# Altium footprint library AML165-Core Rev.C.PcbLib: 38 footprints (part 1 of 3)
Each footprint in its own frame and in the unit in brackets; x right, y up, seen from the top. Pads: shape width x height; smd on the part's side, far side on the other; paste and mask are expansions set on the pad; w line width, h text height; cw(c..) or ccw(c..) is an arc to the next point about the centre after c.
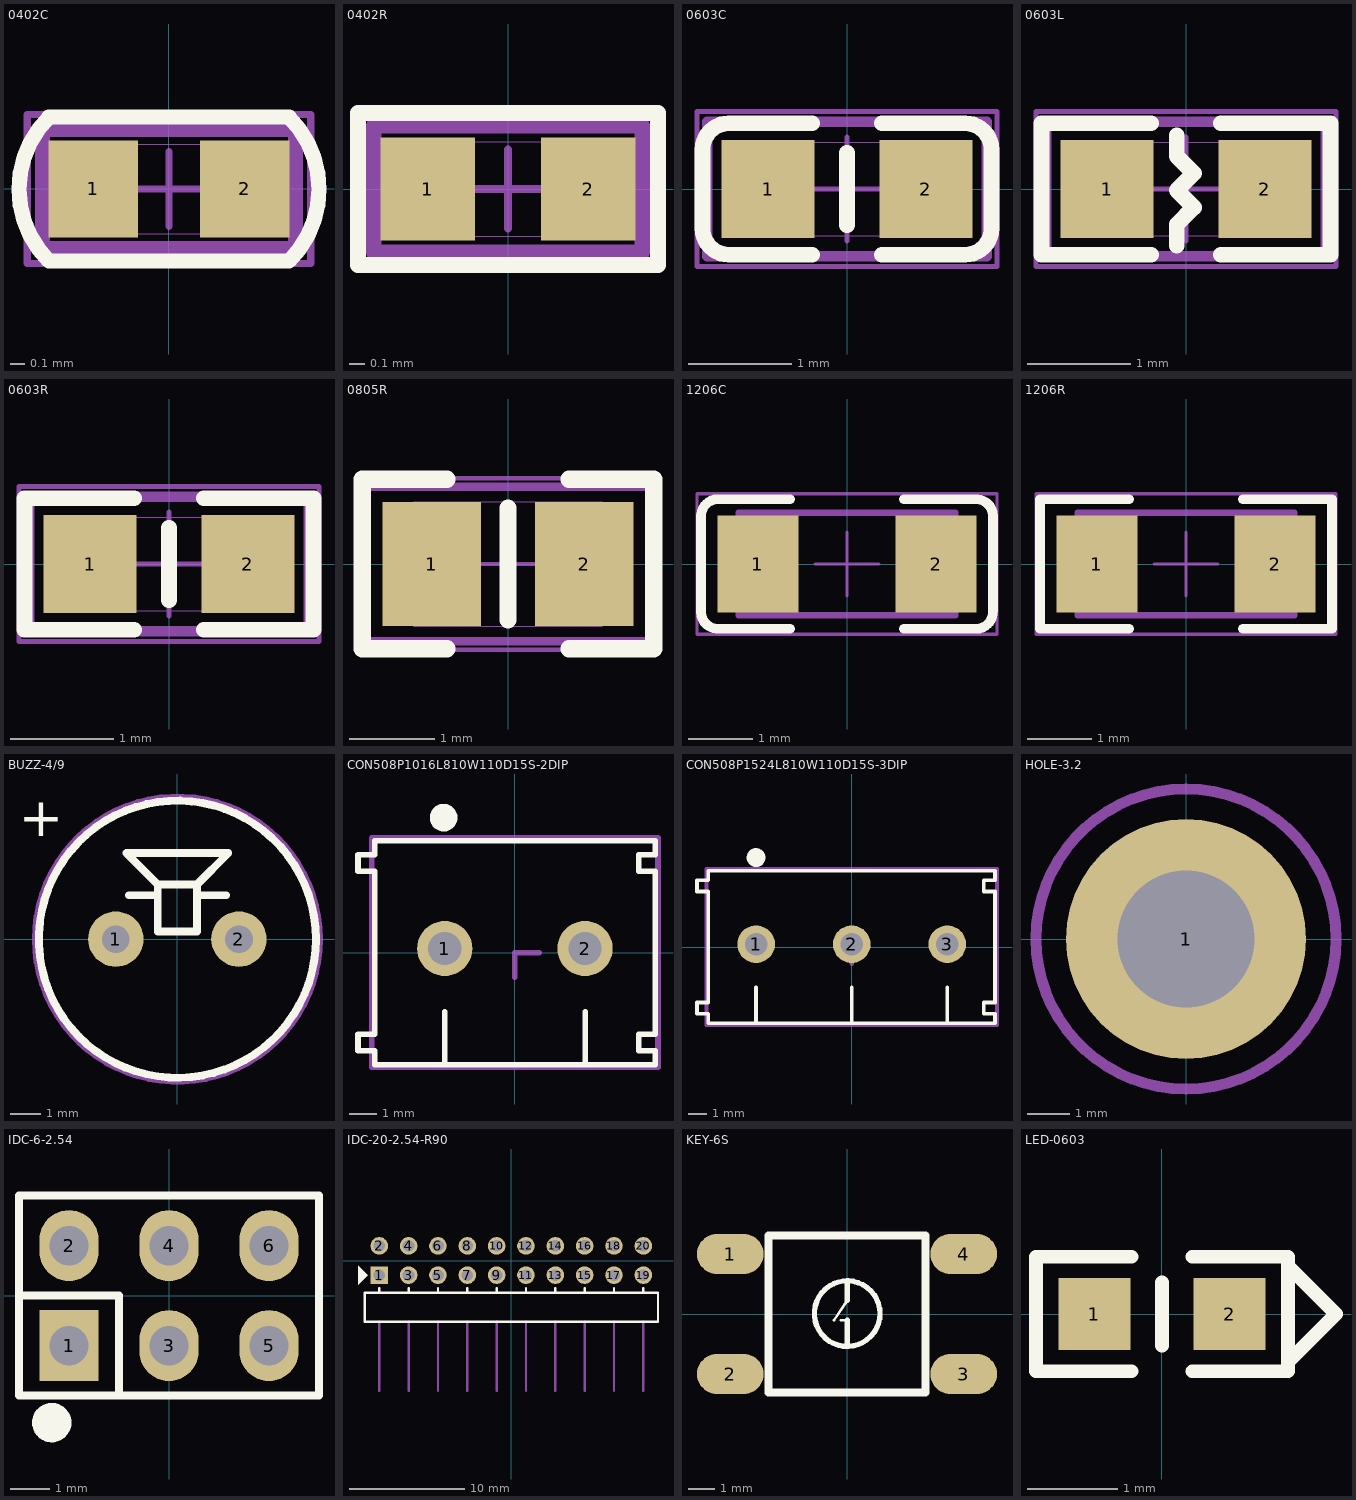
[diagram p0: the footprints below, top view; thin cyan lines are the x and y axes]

## 0402C [mm]
height 0.635
pads (2):
  rect 0.6x0.65 smd mask+0.025: 1(-0.508,0) 2(0.508,0)
Top Overlay:
  lines w0.102: -0.807,0.482 ccw(c-0.326,0) -0.806,-0.483 0.806,-0.483 ccw(c0.326,0) 0.807,0.482 0.806,0.483 -0.806,0.483 -0.807,0.482
Mechanical 15:
  lines w0.1: -0.85,-0.4 -0.85,0.4 0.85,0.4 0.85,-0.4 -0.85,-0.4
Mechanical 16:
  lines w0.001: -0.55,-0.3 -0.55,0.3 0.55,0.3 0.55,-0.3 -0.55,-0.3
  lines w0.05: -0.25,0 0.25,0 ; 0,-0.25 0,0.25 ; -0.95,-0.5 -0.95,0.5 0.95,0.5 0.95,-0.5 -0.95,-0.5
3D body: height 0.5, standoff 0, extent -0.508,-0.229 0.492,0.271

## 0402R [mm]
height 0.635
pads (2):
  rect 0.6x0.65 smd mask+0.025: 1(-0.508,0) 2(0.508,0)
Top Overlay:
  lines w0.102: -0.95,-0.483 0.95,-0.483 0.95,0.483 -0.95,0.483 -0.95,-0.483
Mechanical 15:
  lines w0.1: -0.85,-0.4 -0.85,0.4 0.85,0.4 0.85,-0.4 -0.85,-0.4
Mechanical 16:
  lines w0.001: -0.55,-0.3 -0.55,0.3 0.55,0.3 0.55,-0.3 -0.55,-0.3
  lines w0.05: -0.25,0 0.25,0 ; 0,-0.25 0,0.25 ; -0.95,-0.5 -0.95,0.5 0.95,0.5 0.95,-0.5 -0.95,-0.5
3D body: height 0.35, standoff 0, extent -0.475,-0.254 0.525,0.246

## 0603C [mm]
pads (2):
  rect 0.9x0.95 smd: 1(-0.762,0) 2(0.762,0)
Top Overlay:
  lines w0.152: -0.337,-0.635 -1.143,-0.635 cw(c-1.143,-0.381) -1.397,-0.381 -1.397,0.381 cw(c-1.143,0.381) -1.143,0.635 -0.337,0.635 ; 0,-0.35 0,0.35 ; 0.337,-0.635 1.143,-0.635 ccw(c1.143,-0.381) 1.397,-0.381 1.397,0.381 ccw(c1.143,0.381) 1.143,0.635 0.337,0.635
Mechanical 15:
  lines w0.1: -1.35,-0.65 -1.35,0.65 1.35,0.65 1.35,-0.65 -1.35,-0.65
Mechanical 16:
  lines w0.001: -0.85,-0.45 -0.85,0.45 0.85,0.45 0.85,-0.45 -0.85,-0.45
  lines w0.05: -0.5,0 0.5,0 ; 0,-0.5 0,0.5 ; -1.45,-0.75 -1.45,0.75 1.45,0.75 1.45,-0.75 -1.45,-0.75
3D body: height 0.3, standoff 0, extent -0.789,-0.381 0.811,0.419

## 0603L [mm] "Chip Inductor, 2-Leads, Body 2.50x2.00mm, IPC Medium Density"
height 1
pads (2):
  rect 0.9x0.95 smd: 1(-0.762,0) 2(0.762,0)
Top Overlay:
  lines w0.152: -0.337,-0.635 -1.397,-0.635 -1.397,0.635 -0.337,0.635 ; -0.089,-0.546 -0.089,-0.343 0.076,-0.178 -0.089,-0.013 0.076,0.152 -0.089,0.318 -0.089,0.521 ; 0.337,-0.635 1.397,-0.635 1.397,0.635 0.337,0.635
Mechanical 15:
  lines w0.1: -1.35,-0.65 -1.35,0.65 1.35,0.65 1.35,-0.65 -1.35,-0.65
Mechanical 16:
  lines w0.001: -0.85,-0.45 -0.85,0.45 0.85,0.45 0.85,-0.45 -0.85,-0.45
  lines w0.05: -0.5,0 0.5,0 ; 0,-0.5 0,0.5 ; -1.45,-0.75 -1.45,0.75 1.45,0.75 1.45,-0.75 -1.45,-0.75
3D body: height 0.3, standoff 0, extent -0.8,-0.4 0.8,0.4

## 0603R [mm]
pads (2):
  rect 0.9x0.95 smd: 1(-0.762,0) 2(0.762,0)
Top Overlay:
  lines w0.152: -0.337,-0.635 -1.397,-0.635 -1.397,0.635 -0.337,0.635 ; 0,-0.35 0,0.35 ; 0.337,-0.635 1.397,-0.635 1.397,0.635 0.337,0.635
Mechanical 15:
  lines w0.1: -1.35,-0.65 1.35,-0.65 1.35,0.65 -1.35,0.65 -1.35,-0.65
Mechanical 16:
  lines w0.001: -0.85,-0.45 0.85,-0.45 0.85,0.45 -0.85,0.45 -0.85,-0.45
  lines w0.05: -0.5,0 0.5,0 ; 0,-0.5 0,0.5 ; -1.45,-0.75 1.45,-0.75 1.45,0.75 -1.45,0.75 -1.45,-0.75
3D body: height 0.3, standoff 0, extent -0.8,-0.4 0.8,0.4

## 0805R [mm]
height 1.905
pads (2):
  rect 1.15x1.45 smd: 1(-0.889,0) 2(0.889,0)
Top Overlay:
  lines w0.2: 0,-0.65 0,0.65
  lines w0.203: -0.711,-0.991 -1.702,-0.991 -1.702,0.991 -0.711,0.991 ; 0.711,-0.991 1.702,-0.991 1.702,0.991 0.711,0.991
Mechanical 15:
  lines w0.1: -1.65,-0.9 1.65,-0.9 1.65,0.9 -1.65,0.9 -1.65,-0.9
Mechanical 16:
  lines w0.001: -1.1,-0.725 1.1,-0.725 1.1,0.725 -1.1,0.725 -1.1,-0.725
  lines w0.05: -0.5,0 0.5,0 ; 0,-0.5 0,0.5 ; -1.75,-1 1.75,-1 1.75,1 -1.75,1 -1.75,-1
3D body: height 0.78, standoff 0, extent -1,-0.625 1,0.625

## 1206C [mil] "元件 长X宽=120X60mil"
height 40
pads (2):
  rect 50x60 smd: 1(-55,0) 2(55,0)
Top Overlay:
  lines w6: -90,29 cw(c-79.5,29.5) -80,40 -35,40 ; -90,30 -90,-30 ccw(c-79.5,-29.5) -79,-40 ; -80,-40 -35,-40 ; 35,-40 79,-40 ; 35,40 80,40 ; 79,40 cw(c79.5,29.5) 90,30 90,-29 cw(c79.5,-29.5) 80,-40
Mechanical 15:
  lines w3.94: -66.93,-31.5 66.93,-31.5 66.93,31.5 -66.93,31.5 -66.93,-31.5
Mechanical 16:
  lines w0.04: -66.93,-31.5 66.93,-31.5 66.93,31.5 -66.93,31.5 -66.93,-31.5
  lines w1.97: -19.68,0 19.68,0 ; 0,-19.68 0,19.68 ; -92.52,-43.31 92.52,-43.31 92.52,43.31 -92.52,43.31 -92.52,-43.31
3D body: height 39.37, standoff 0, extent -62,-32 63.98,30.99

## 1206R [mil] "元件 长X宽=120X60mil"
height 40
pads (2):
  rect 50x60 smd: 1(-55,0) 2(55,0)
Top Overlay:
  lines w6: -35,-40 -90,-40 -90,40 -35,40 ; 35,-40 90,-40 90,40 35,40
Mechanical 15:
  lines w3.94: -66.93,-31.5 -66.93,31.5 66.93,31.5 66.93,-31.5 -66.93,-31.5
Mechanical 16:
  lines w0.04: -66.93,-31.5 -66.93,31.5 66.93,31.5 66.93,-31.5 -66.93,-31.5
  lines w1.97: -19.68,0 19.68,0 ; 0,-19.68 0,19.68 ; -92.52,-43.31 -92.52,43.31 92.52,43.31 92.52,-43.31 -92.52,-43.31
3D body: height 23.62, standoff 0, extent -62.93,-31.5 63.06,31.5

## BUZZ-4/9 [mm]
height 5
pads (2):
  round 1.8 hole 0.9: 1(-2,0) 2(2,0)
Top Overlay:
  circle w0.254: c0,0 r4.5
  lines w0.254: -1.575,1.424 -0.635,1.424 ; 0.635,1.424 1.575,1.424 ; -0.635,1.778 -0.635,0.254 0.635,0.254 0.635,1.778 ; -0.635,1.778 -1.651,2.794 1.651,2.794 0.635,1.778 ; -0.635,1.778 0.635,1.778
  text "+" at -5.144,3.341 h1.27
Mechanical 15:
  circle w0.254: c0,0 r4.6

## CON508P1016L810W110D15S-2DIP [mm]
height 10.1
pads (2):
  round 2 hole 1.2: 1(-2.54,0.15) 2(2.54,0.15)
Top Overlay:
  circle w0.5: c-2.581,4.888 r0.25
  lines w0.2: -2.54,-4.05 -2.54,-2.136 ; 2.54,-4.05 2.54,-2.136 ; -5.68,-3.55 -5.68,-2.95 -5.08,-2.95 -5.08,2.95 -5.68,2.95 -5.68,3.55 -5.08,3.55 -5.08,4.05 5.08,4.05 5.08,3.55 4.48,3.55 4.48,2.95 5.08,2.95 5.08,-2.95 4.48,-2.95 4.48,-3.55 5.08,-3.55 5.08,-4.05 -5.08,-4.05 -5.08,-3.55 -5.68,-3.55
Mechanical 15:
  lines w0.2: 0,-0.889 0,0 0.889,0 ; -5.18,-4.15 5.18,-4.15 5.18,4.15 -5.18,4.15 -5.18,-4.15

## CON508P1524L810W110D15S-3DIP [mm]
height 10.1
pads (3):
  round 2 hole 1.2: 1(-5.08,0.15) 2(0,0.15) 3(5.08,0.15)
Top Overlay:
  circle w0.5: c-5.08,4.754 r0.25
  lines w0.2: -5.08,-4.05 -5.08,-2.136 ; 0,-4.05 0,-2.136 ; 5.08,-4.05 5.08,-2.136 ; -8.22,-3.55 -7.62,-3.55 -7.62,-4.05 7.62,-4.05 7.62,-3.55 7.02,-3.55 7.02,-2.95 7.62,-2.95 7.62,2.95 7.02,2.95 7.02,3.55 7.62,3.55 7.62,4.05 -7.62,4.05 -7.62,3.55 -8.22,3.55 -8.22,2.95 -7.62,2.95 -7.62,-2.95 -8.22,-2.95 -8.22,-3.55
Mechanical 15:
  lines w0.2: -7.72,-4.15 -7.72,4.15 7.72,4.15 7.72,-4.15 -7.72,-4.15
  lines w0.254: 0,-0.889 0,0 0.889,0

## HOLE-3.2 [mm]
pads (1):
  round 5.6 hole 3.2: 1(0,0)
Mechanical 15:
  circle w0.254: c0,0 r3.5

## IDC-6-2.54 [mm]
pads (6):
  rect 1.5x1.8 hole 1: 1(-2.54,-1.27)
  oval 1.5x1.8 hole 1: 2(-2.54,1.27) 3(0,-1.27) 4(0,1.27) 5(2.54,-1.27) 6(2.54,1.27)
Top Overlay:
  circle w0.5: c-2.979,-3.226 r0.25
  lines w0.2: -3.81,0 -1.27,0 -1.27,-2.54 ; -3.81,-2.54 3.81,-2.54 3.81,2.54 -3.81,2.54 -3.81,-2.54
3D body: height 7.58, standoff -2.94, extent 1.27,-2.54 3.81,0
3D body: height 7.58, standoff -2.94, extent 1.27,0 3.81,2.54
3D body: height 7.58, standoff -2.94, extent -1.27,-2.54 1.27,0
3D body: height 7.58, standoff -2.94, extent -3.81,-2.54 -1.27,0
3D body: height 7.58, standoff -2.94, extent -1.27,0 1.27,2.54
3D body: height 7.58, standoff -2.94, extent -3.81,0 -1.27,2.54

## IDC-20-2.54-R90 [mil]
pads (20):
  rect 60x60 / inner rect 60x70 / far side rect 60x70 hole 40: 1(-450,-50)
  round 60 / inner oval 60x70 / far side oval 60x70 hole 40: 2(-450,50) 3(-350,-50) 4(-350,50) 5(-250,-50) 6(-250,50) 7(-150,-50) 8(-150,50) 9(-50,-50) 10(-50,50) 11(50,-50) 12(50,50) 15(250,-50) 16(250,50) 17(350,-50) 18(350,50) 19(450,-50) 20(450,50)
  round 60 / inner round 60 / far side oval 60x64 hole 40: 13(150,-50) 14(150,50)
Top Overlay:
  region: -490,-50 -522.5,-17.5 -522.5,-82.5
  lines w8: -450,-109.84 -450,-94.49 ; -350,-109.84 -350,-94.49 ; -250,-109.84 -250,-94.49 ; -150,-109.84 -150,-94.49 ; -50,-109.84 -50,-94.49 ; 50,-109.84 50,-94.49 ; 150,-109.84 150,-94.49 ; 250,-109.84 250,-94.49 ; 350,-109.84 350,-94.49 ; 450,-109.84 450,-94.49 ; -500,-208.27 500,-208.27 500,-109.84 -500,-109.84 -500,-208.27
Mechanical 15:
  lines w8: -450,-444.49 -450,-208.27 ; -350,-444.49 -350,-208.27 ; -250,-444.49 -250,-208.27 ; -150,-444.49 -150,-208.27 ; -50,-444.49 -50,-208.27 ; 50,-444.49 50,-208.27 ; 150,-444.49 150,-208.27 ; 250,-444.49 250,-208.27 ; 350,-444.49 350,-208.27 ; 450,-444.49 450,-208.27

## KEY-6S [mil]
height 120
pads (4):
  oval 100x60 smd: 1(-175,90) 2(-175,-90) 3(175,-90) 4(175,90)
Top Overlay:
  lines w4: -19.42,-9.24 0.27,20.29 ; -9.57,-9.24 0.27,-9.24
  lines w8: 0.27,-48.61 0.27,-9.23 ; 0.27,20.29 0.27,49.82 ; 49.48,0.61 ccw(c0.27,0.61) 49.48,0.61
  lines w12: -118.11,-118.11 -118.11,118.11 118.11,118.11 118.11,-118.11 -118.11,-118.11
3D body: height 267.87, standoff 2.13, extent -200.64,-122.05 200.65,122.05

## LED-0603 [mm] "20100324  贴片0603LED   LSB"
height 0.889
pads (2):
  rect 0.8x0.8 smd: 1(-0.75,0) 2(0.75,0)
Top Overlay:
  lines w0.152: -0.337,-0.635 -1.397,-0.635 -1.397,0.635 -0.337,0.635 ; 0,-0.35 0,0.35 ; 0.337,-0.635 1.397,-0.635 1.397,0.635 0.337,0.635 ; 1.397,-0.533 1.93,0 1.397,0.533
3D body: height 0.3, standoff 0, extent -0.8,-0.4 0.8,0.4
3D body: height 0.4, standoff 0, extent -0.5,-0.403 0.5,0.403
